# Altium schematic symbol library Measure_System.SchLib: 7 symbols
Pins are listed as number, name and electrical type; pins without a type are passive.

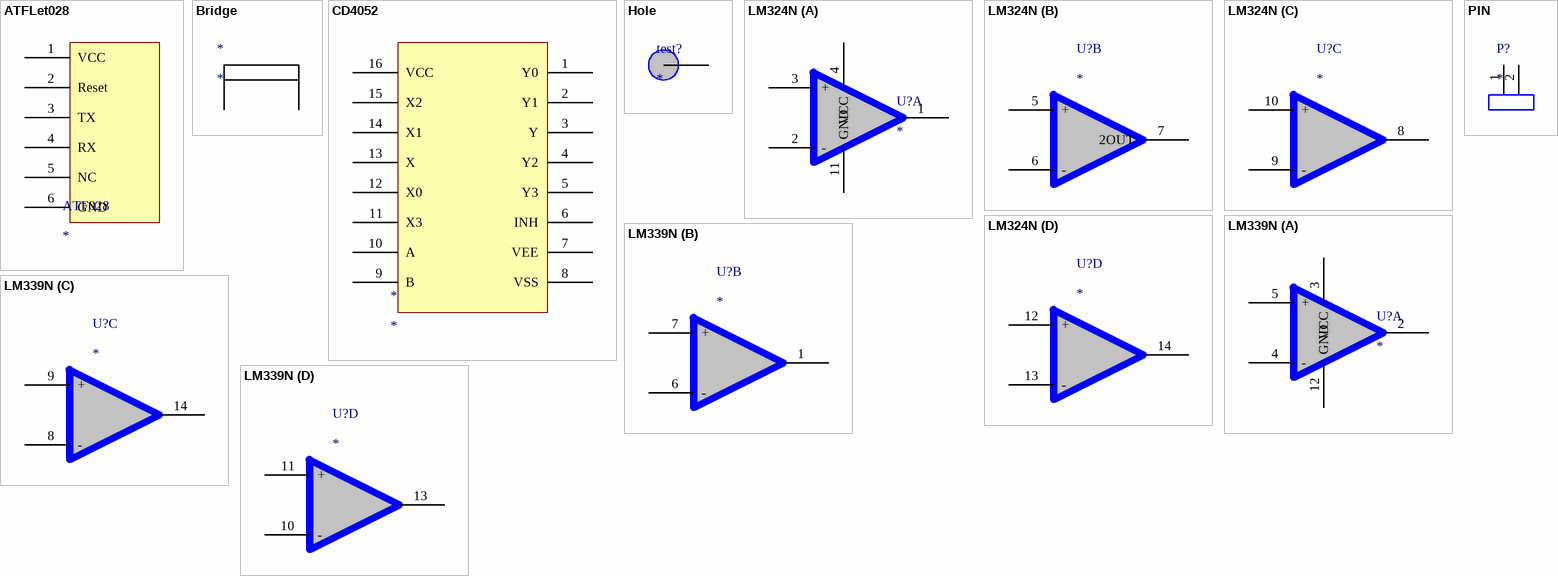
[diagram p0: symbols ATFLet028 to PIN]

## ATFLet028
designator ATF028
footprint ATFLet028
pins: 1 VCC, 2 Reset, 3 TX, 4 RX, 5 NC, 6 GND

## Bridge
designator *
footprint Bridge
pins: 1 46, 2 47

## CD4052
designator *
footprint CD4052
pins: 1 Y0, 2 Y1, 3 Y, 4 Y2, 5 Y3, 6 INH, 7 VEE, 8 VSS, 9 B, 10 A, 11 X3, 12 X0, 13 X, 14 X1, 15 X2, 16 VCC

## Hole
designator test?
footprint Hole
pins: 1 ~PR

## LM324N
designator U?
footprint LM324N
part A pins: 1 1OUT, 2 -, 3 +, 4 VCC, 11 GND
part B pins: 5 +, 6 -, 7 2OUT
part C pins: 8 3OUT, 9 -, 10 +
part D pins: 12 +, 13 -, 14 4OUT

## LM339N
designator U?
footprint LM339N
part A pins: 2 1OUT, 3 VCC, 4 -, 5 +, 12 GND
part B pins: 1 2OUT, 6 -, 7 +
part C pins: 8 -, 9 +, 14 3OUT
part D pins: 10 -, 11 +, 13 4OUT

## PIN
designator P?
footprint PIN
pins: 1, 2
